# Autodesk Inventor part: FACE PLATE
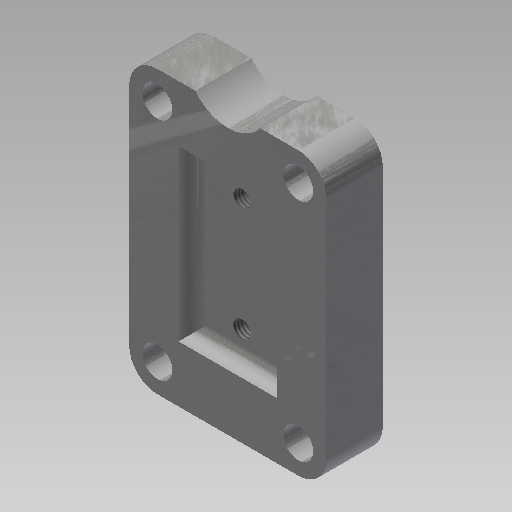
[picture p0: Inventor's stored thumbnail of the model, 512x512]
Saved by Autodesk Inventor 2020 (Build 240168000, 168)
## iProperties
Part Number: FACE PLATE
Document SubType Name: Modeling
Created: 2003-11
Designer: Autodesk, Inc.
Manufacturer: Standard
Standards Organization: Custom
Mass: 239.081 g
Surface Area: 93.2455 cm^2
Volume: 30.4562 cm^3
Density: 7.85 g/cm^3
Material: Steel, Mild
Appearance: Steel
Control State: 0
Master: False
Checked Out: False
Shininess: 64.0
Length Units: 11272
Angle Units: 11279
Time Units: 11290
Mass Units: 11286
Length Display Precision: 3
Angle Display Precision: 2
Compacted: True
Density: 0.0
Volumn: 0.0
Area: 0.0
PropertySet Name: Model Information
Author: Autodesk, Inc.
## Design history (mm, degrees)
sketch "Sketch1"
  geometry: L1 (0, 0)-(44.45, 0); L2 (44.45, 0)-(44.45, 63.5); L3 (44.45, 63.5)-(0, 63.5); L4 (0, 63.5)-(0, 0)
  constraints: 8 end point, 2 parallel, 1 horizontal, 1 perpendicular
  dimensions: "d0" = 44.45 distance between parallel lines of L2 L4; "d1" = 63.5 distance of L1.end L2.end
extrude "Extrusion1" new body sketch "Sketch1" distance "d2" = 12.7; taper "d3" = 0 deg
sketch "Sketch2"
  geometry: L1 (0, 0)-(0, 63.5) reference; L2 (44.45, 0)-(0, 0) reference; L3 (44.45, 63.5)-(44.45, 0) reference; L4 (0, 63.5)-(44.45, 63.5) reference; L5 (0, 31.75)-(44.45, 31.75); 4 further points
  constraints: 2 end point, 2 midpoint, 2 symmetric about line
  dimensions: "d4" = 6.35 distance from line of point (6.35, 57.15) L4; "d5" = 6.35 distance from line of L4 point (38.1, 57.15); "d6" = 6.35 distance from line of L1 point (6.35, 57.15); "d7" = 6.35 distance from line of L3 point (38.1, 57.15)
hole "Hole1" sketch "Sketch2" at (6.35, 57.15), (38.1, 57.15), (6.35, 6.35), (38.1, 6.35) diameter "d8" = 6.731; stored, may be unused: countersink angle "d12" = 82 deg, drill point angle "d14" = 118 deg; dims "d9" = 12.7, "d10" = 9.525, "d11" = 6.35, "d13" = 19.05
fillet "Fillet1" dims "d15" = 6.35
sketch "Sketch3"
  geometry: L1 (11.125, 50.8)-(33.35, 50.8); L2 (33.35, 50.8)-(33.35, 12.7); L3 (33.35, 12.7)-(11.125, 12.7); L4 (11.125, 12.7)-(11.125, 50.8); L5 (44.45, 57.15)-(44.45, 6.35) reference; L6 (38.1, 0)-(6.35, 0) reference
  constraints: 8 end point, 2 parallel, 1 horizontal, 1 perpendicular
  dimensions: "d16" = 11.0998 distance between parallel lines of L5 L2; "d17" = 22.225 distance between parallel lines of L2 L4; "d18" = 12.7 distance between parallel lines of L6 L3; "d19" = 38.1 distance between parallel lines of L3 L1
extrude "Extrusion2" cut sketch "Sketch3" distance "d20" = 3.175; taper "d21" = 0 deg
sketch "Sketch4"
  geometry: L1 (14.3, 15.875)-(14.3, 47.625) reference; L2 (30.175, 47.625)-(30.175, 15.875) reference; L3 (14.3, 47.625)-(30.175, 47.625) reference; L4 (14.3, 31.75)-(30.175, 31.75); L5 (30.175, 15.875)-(14.3, 15.875) reference; C1 r 3.365 at (6.35, 57.15) reference; 1 further point
  constraints: 2 end point, 2 midpoint
  dimensions: "d23" = 15.875 horizontal distance of C1.centre point (22.225, 44.45); "d24" = 12.7 vertical distance of point (22.225, 44.45) C1.centre
hole "Hole2" sketch "Sketch4" at (22.225, 44.45) diameter "d25" = 3.9624; stored, may be unused: countersink angle "d29" = 82 deg, drill point angle "d31" = 118 deg; dims "d26" = 12.7, "d27" = 9.525, "d28" = 6.35, "d30" = 19.05
workplane "Work Plane1"
mirror "Mirror1"
sketch "Sketch5"
  geometry: C1 r 9.274 at (-22.225, 69.17)
  constraints: 1 centre point
extrude "Extrusion3" cut sketch "Sketch5" extent not by distance; stored distance "d33" = 25.4; taper "d34" = 0 deg
fillet "Fillet3" dims "d39" = 3.175
body "Solid1"
node "Projected Loop1"
other parameters: "d32" = -31.75, "d35" = 0, "d36" = 0, "d37" = 0, "d38" = 0
